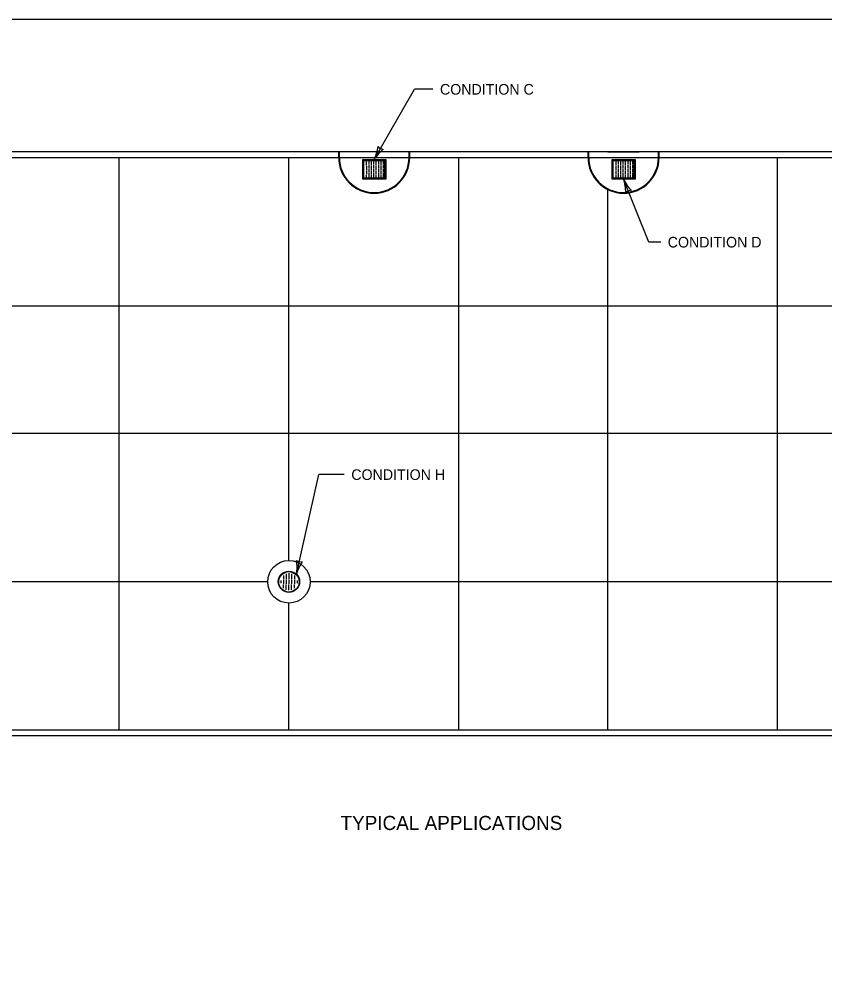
# Model space of a CAD drawing. Extents: x 49991.4 to 50029.7, y 49987.6 to 50011.4.
# Drawn here: x 50005.69 to 50010.24, y 49993.55 to 49999 of the extents above; entities that cross this region are included whole.
import ezdxf

# ---------------------------------------------------------------- set-up
doc = ezdxf.new("R2010")
doc.units = 0
for name, color, linetype in [('Level 1', 7, 'Continuous'), ('Level 18', 7, 'Continuous'), ('Level 2', 7, 'Continuous'), ('Level 3', 7, 'Continuous')]:
    doc.layers.add(name, color=color, linetype=linetype)

msp = doc.modelspace()

# ---------------------------------------------------------------- linework, layer by layer
at = {"layer": 'Level 1'}
for p, q in [((50005.8148, 49998.2482), (49999.9583, 49998.2482)), ((50016.2033, 49998.2482), (50005.8148, 49998.2482)), ((50007.4923, 49998.2157), (50007.4923, 49998.2482)), ((50007.496, 49998.2157), (50007.496, 49998.2482)), ((50007.89, 49998.2157), (50007.89, 49998.2482)), ((50007.8938, 49998.2157), (50007.8938, 49998.2482)), ((50008.9025, 49998.2157), (50008.9025, 49998.2482)), ((50008.9063, 49998.2157), (50008.9063, 49998.2482)), ((50009.3003, 49998.2157), (50009.3003, 49998.2482)), ((50009.304, 49998.2157), (50009.304, 49998.2482)), ((50005.8148, 49998.2157), (49999.9583, 49998.2157)), ((50016.2033, 49998.2157), (50005.8148, 49998.2157)), ((50006.2508, 49994.9757), (50006.2508, 49998.2157)), ((50007.2108, 49995.9359), (50007.2108, 49998.2157)), ((50007.628, 49998.0951), (50007.628, 49998.2051)), ((50007.628, 49998.2051), (50007.758, 49998.2051)), ((50007.6324, 49998.2007), (50007.6324, 49998.0995)), ((50007.633, 49998.1999), (50007.6324, 49998.2007)), ((50007.7536, 49998.2007), (50007.6324, 49998.2007)), ((50007.6485, 49998.1943), (50007.6485, 49998.1718)), ((50007.6621, 49998.1943), (50007.6621, 49998.1818)), ((50007.6757, 49998.1943), (50007.6757, 49998.1718)), ((50007.6893, 49998.1943), (50007.6893, 49998.1818)), ((50007.7029, 49998.1943), (50007.7029, 49998.1718)), ((50007.7165, 49998.1943), (50007.7165, 49998.1818)), ((50007.7301, 49998.1943), (50007.7301, 49998.1718)), ((50007.7437, 49998.1943), (50007.7437, 49998.1818)), ((50007.7536, 49998.2007), (50007.753, 49998.1999)), ((50007.753, 49998.0999), (50007.753, 49998.1999)), ((50007.7536, 49998.0995), (50007.7536, 49998.2007)), ((50007.758, 49998.2051), (50007.758, 49998.0951)), ((50008.1708, 49994.9757), (50008.1708, 49998.2157)), ((50009.0383, 49998.0951), (50009.0383, 49998.2051)), ((50009.0383, 49998.2051), (50009.1683, 49998.2051)), ((50009.0426, 49998.2007), (50009.0426, 49998.0995)), ((50009.0433, 49998.1999), (50009.0426, 49998.2007)), ((50009.1639, 49998.2007), (50009.0426, 49998.2007)), ((50009.0588, 49998.1943), (50009.0588, 49998.1718)), ((50009.0724, 49998.1943), (50009.0724, 49998.1818)), ((50009.086, 49998.1943), (50009.086, 49998.1718)), ((50009.0996, 49998.1943), (50009.0996, 49998.1818)), ((50009.1132, 49998.1943), (50009.1132, 49998.1718)), ((50009.1268, 49998.1943), (50009.1268, 49998.1818)), ((50009.1403, 49998.1943), (50009.1403, 49998.1718)), ((50009.1539, 49998.1943), (50009.1539, 49998.1818)), ((50009.1639, 49998.2007), (50009.1633, 49998.1999)), ((50009.1633, 49998.0999), (50009.1633, 49998.1999)), ((50009.1639, 49998.0995), (50009.1639, 49998.2007)), ((50009.1683, 49998.2051), (50009.1683, 49998.0951)), ((50009.9745, 49994.9757), (50009.9745, 49998.2157)), ((50007.6486, 49998.1681), (50007.6486, 49998.1468)), ((50007.6486, 49998.1431), (50007.6486, 49998.1218)), ((50007.6621, 49998.178), (50007.6621, 49998.1568)), ((50007.6621, 49998.1531), (50007.6621, 49998.1318)), ((50007.6757, 49998.1681), (50007.6757, 49998.1468)), ((50007.6757, 49998.1431), (50007.6757, 49998.1218)), ((50007.6893, 49998.178), (50007.6893, 49998.1568)), ((50007.6893, 49998.1531), (50007.6893, 49998.1318)), ((50007.7029, 49998.1681), (50007.7029, 49998.1468)), ((50007.7029, 49998.1431), (50007.7029, 49998.1218)), ((50007.7165, 49998.178), (50007.7165, 49998.1568)), ((50007.7165, 49998.1531), (50007.7165, 49998.1318)), ((50007.7301, 49998.1681), (50007.7301, 49998.1468)), ((50007.7301, 49998.1431), (50007.7301, 49998.1218)), ((50007.7437, 49998.178), (50007.7437, 49998.1568)), ((50007.7437, 49998.1531), (50007.7437, 49998.1318)), ((50009.0588, 49998.1681), (50009.0588, 49998.1468)), ((50009.0588, 49998.1431), (50009.0588, 49998.1218)), ((50009.0724, 49998.178), (50009.0724, 49998.1568)), ((50009.0724, 49998.1531), (50009.0724, 49998.1318)), ((50009.086, 49998.1681), (50009.086, 49998.1468)), ((50009.086, 49998.1431), (50009.086, 49998.1218)), ((50009.0996, 49998.178), (50009.0996, 49998.1568)), ((50009.0996, 49998.1531), (50009.0996, 49998.1318)), ((50009.1132, 49998.1681), (50009.1132, 49998.1468)), ((50009.1132, 49998.1431), (50009.1132, 49998.1218)), ((50009.1268, 49998.178), (50009.1268, 49998.1568)), ((50009.1268, 49998.1531), (50009.1268, 49998.1318)), ((50009.1403, 49998.1681), (50009.1403, 49998.1468)), ((50009.1403, 49998.1431), (50009.1403, 49998.1218)), ((50009.1539, 49998.178), (50009.1539, 49998.1568)), ((50009.1539, 49998.1531), (50009.1539, 49998.1318)), ((50007.758, 49998.0951), (50007.628, 49998.0951)), ((50007.633, 49998.0999), (50007.6324, 49998.0995)), ((50007.6324, 49998.0995), (50007.7536, 49998.0995)), ((50007.633, 49998.0999), (50007.753, 49998.0999)), ((50007.6485, 49998.1181), (50007.6485, 49998.1056)), ((50007.6621, 49998.1281), (50007.6621, 49998.1056)), ((50007.6757, 49998.1181), (50007.6757, 49998.1056)), ((50007.6893, 49998.1281), (50007.6893, 49998.1056)), ((50007.7029, 49998.1181), (50007.7029, 49998.1056)), ((50007.7165, 49998.1281), (50007.7165, 49998.1056)), ((50007.7298, 49998.0995), (50007.7524, 49998.0995)), ((50007.7301, 49998.1181), (50007.7301, 49998.1056)), ((50007.7437, 49998.1281), (50007.7437, 49998.1056)), ((50007.7536, 49998.0995), (50007.753, 49998.0999)), ((50009.1683, 49998.0951), (50009.0383, 49998.0951)), ((50009.0433, 49998.0999), (50009.0426, 49998.0995)), ((50009.0426, 49998.0995), (50009.1639, 49998.0995)), ((50009.0433, 49998.0999), (50009.1633, 49998.0999)), ((50009.0588, 49998.1181), (50009.0588, 49998.1056)), ((50009.0724, 49998.1281), (50009.0724, 49998.1056)), ((50009.086, 49998.1181), (50009.086, 49998.1056)), ((50009.0996, 49998.1281), (50009.0996, 49998.1056)), ((50009.1132, 49998.1181), (50009.1132, 49998.1056)), ((50009.1268, 49998.1281), (50009.1268, 49998.1056)), ((50009.1401, 49998.0995), (50009.1626, 49998.0995)), ((50009.1403, 49998.1181), (50009.1403, 49998.1056)), ((50009.1539, 49998.1281), (50009.1539, 49998.1056)), ((50009.1639, 49998.0995), (50009.1633, 49998.0999)), ((50009.0145, 49994.9757), (50009.0145, 49998.0357)), ((50016.2033, 49997.3757), (50000.0029, 49997.3757)), ((50011.8945, 49996.6557), (50000.0029, 49996.6557)), ((50007.1801, 49995.8522), (50007.1801, 49995.8311)), ((50007.1954, 49995.8611), (50007.1954, 49995.8311)), ((50007.2108, 49995.8638), (50007.2108, 49995.8311)), ((50007.2261, 49995.8611), (50007.2261, 49995.8311)), ((50007.2414, 49995.8522), (50007.2414, 49995.8311)), ((50007.0905, 49995.8157), (50004.5061, 49995.8157)), ((50007.1648, 49995.8237), (50007.1648, 49995.8077)), ((50007.1801, 49995.8267), (50007.1801, 49995.8048)), ((50007.1801, 49995.7793), (50007.1801, 49995.8004)), ((50007.1954, 49995.8267), (50007.1954, 49995.8048)), ((50007.1954, 49995.7703), (50007.1954, 49995.8004)), ((50007.2108, 49995.8267), (50007.2108, 49995.8048)), ((50007.2108, 49995.7677), (50007.2108, 49995.8004)), ((50007.2261, 49995.8267), (50007.2261, 49995.8048)), ((50007.2261, 49995.7703), (50007.2261, 49995.8004)), ((50007.2414, 49995.8267), (50007.2414, 49995.8048)), ((50007.2414, 49995.7793), (50007.2414, 49995.8004)), ((50007.2567, 49995.8237), (50007.2567, 49995.8077)), ((50016.2033, 49995.8157), (50007.331, 49995.8157)), ((50007.2108, 49994.9757), (50007.2108, 49995.6955)), ((50016.2033, 49994.9432), (50004.3261, 49994.9432)), ((50016.2033, 49994.9757), (50004.3308, 49994.9757))]:
    msp.add_line(p, q, dxfattribs=at)
for points in [[(49999.3835, 49998.9992), (50016.7501, 49998.9992), (50016.7501, 49987.7988), (49999.3835, 49987.7988)], [(50007.633, 49998.1999), (50007.753, 49998.1999), (50007.753, 49998.0999), (50007.633, 49998.0999)], [(50009.0433, 49998.1999), (50009.1632, 49998.1999), (50009.1632, 49998.0999), (50009.0433, 49998.0999)]]:
    msp.add_lwpolyline(points, close=True, dxfattribs=at)
msp.add_lwpolyline([(50009.0145, 49998.2482), (50009.192, 49998.2482)], dxfattribs=at)
for radius in [0.1202, 0.0602, 0.0577]:
    msp.add_circle((50007.2108, 49995.8157), radius, dxfattribs=at)
for centre, radius in [((50007.693, 49998.2157), 0.2008), ((50007.693, 49998.2157), 0.197), ((50009.1033, 49998.2157), 0.2008), ((50009.1033, 49998.2157), 0.197)]:
    msp.add_arc(centre, radius, 180, 0, dxfattribs=at)
at = {"layer": 'Level 18'}
for p, q in [((50007.753, 49998.1999), (50007.633, 49998.1999)), ((50007.633, 49998.1999), (50007.633, 49998.0999)), ((50009.1633, 49998.1999), (50009.0433, 49998.1999)), ((50009.0433, 49998.1999), (50009.0433, 49998.0999)), ((50007.628, 49998.0951), (50007.628, 49998.0951)), ((50007.758, 49998.0951), (50007.758, 49998.0951)), ((50009.0383, 49998.0951), (50009.0383, 49998.0951)), ((50009.1683, 49998.0951), (50009.1683, 49998.0951))]:
    msp.add_line(p, q, dxfattribs=at)
at = {"layer": 'Level 3'}
for p, q in [((50007.692, 49998.2051), (50007.9215, 49998.6027)), ((50008.0251, 49998.6027), (50007.9215, 49998.6027)), ((50009.2454, 49997.7376), (50009.1033, 49998.0951)), ((50009.3132, 49997.7376), (50009.2454, 49997.7376)), ((50007.2533, 49995.8583), (50007.3799, 49996.4222)), ((50007.5236, 49996.4222), (50007.3799, 49996.4222))]:
    msp.add_line(p, q, dxfattribs=at)
for centre, radius, start, end in [((50007.4847, 49998.3115), 0.233, 332.8273, 352.0772), ((50007.8798, 49998.0861), 0.2223, 127.456, 147.6395), ((50007.7561, 49998.3161), 0.0548, 222.1388, 257.8612), ((50008.8935, 49998.0216), 0.2223, 359.1361, 19.3196), ((50009.3153, 49998.1918), 0.233, 204.5074, 223.7572), ((50008.8935, 49998.0216), 0.2223, 359.1361, 19.3196), ((50009.3153, 49998.1918), 0.233, 204.5074, 223.7572), ((50009.1506, 49997.976), 0.0548, 93.8189, 129.5412), ((50009.1506, 49997.976), 0.0548, 93.8189, 129.5412), ((50007.0238, 49995.8981), 0.233, 350.1756, 9.4254), ((50007.4681, 49995.8007), 0.2223, 144.8043, 164.9878), ((50007.2814, 49995.9834), 0.0548, 239.4871, 275.2095)]:
    msp.add_arc(centre, radius, start, end, dxfattribs=at)

# ---------------------------------------------------------------- texts
at = {"layer": 'Level 2'}
for s, height, p in [('CONDITION C', 0.06, (50008.0651, 49998.5727)), ('CONDITION D', 0.06, (50009.3532, 49997.7076)), ('CONDITION H', 0.06, (50007.5636, 49996.3922)), ('TYPICAL APPLICATIONS', 0.08, (50007.5026, 49994.4111))]:
    msp.add_text(s, height=height, dxfattribs=at).set_placement(p)

doc.saveas('drawing.dxf')
